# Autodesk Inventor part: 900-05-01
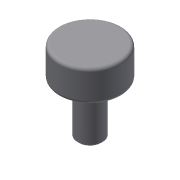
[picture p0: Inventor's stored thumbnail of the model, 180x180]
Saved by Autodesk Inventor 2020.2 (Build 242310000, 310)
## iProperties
Created: 2015-10
Part Number: 900-05-01
Material: Ogólny
Document SubType Name: Modeling
Designer: F.Stasiak
Density: 1 g/cm^3
Appearance: Domyślna
Catalog Web Link: www.expertbooks.pl
Manager: www.cadconsulting.pl
Company: Fabian Stasiak CAD Consulting
Author: F.Stasiak
Subject: Zbiór ćwiczeń. Autodesk Inventor 2020. Kurs Professional
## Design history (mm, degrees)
sketch "Szkic1"
  geometry: C1 r 20 at (0, 0); 1 further point
  constraints: 1 centre point, 1 coincident
  dimensions: "d0" = 40 diameter of C1
extrude "Wyciągnięcie proste1" new body sketch "Szkic1" distance "d1" = 80; taper "d2" = 0 deg
sketch "Szkic2"
  geometry: C1 r 20 at (0, 0) reference; C2 r 50 at (0, 0)
  constraints: 1 centre point, 1 coincident
  dimensions: "d3" = 100 diameter of C2
extrude "Wyciągnięcie proste2" join sketch "Szkic2" distance "d4" = 50; taper "d5" = 0 deg
sketch "Szkic3"
  geometry: C1 r 20 at (0, 0) reference; C2 r 20 at (0, 0) reference; C3 r 30 at (0, 0)
  constraints: 1 centre point, 1 coincident
  dimensions: "d6" = 60 diameter of C3
extrude "Wyciągnięcie proste3" join sketch "Szkic3" distance "d7" = 5; taper "d8" = 0 deg
fillet "Zaokrąglenie1" dims "d9" = 5
chamfer "Faza1" distance "d10" = 3; stored, may be unused: second distance "d11" = 2, angle "d12" = 45 deg
node "Bryła1"
